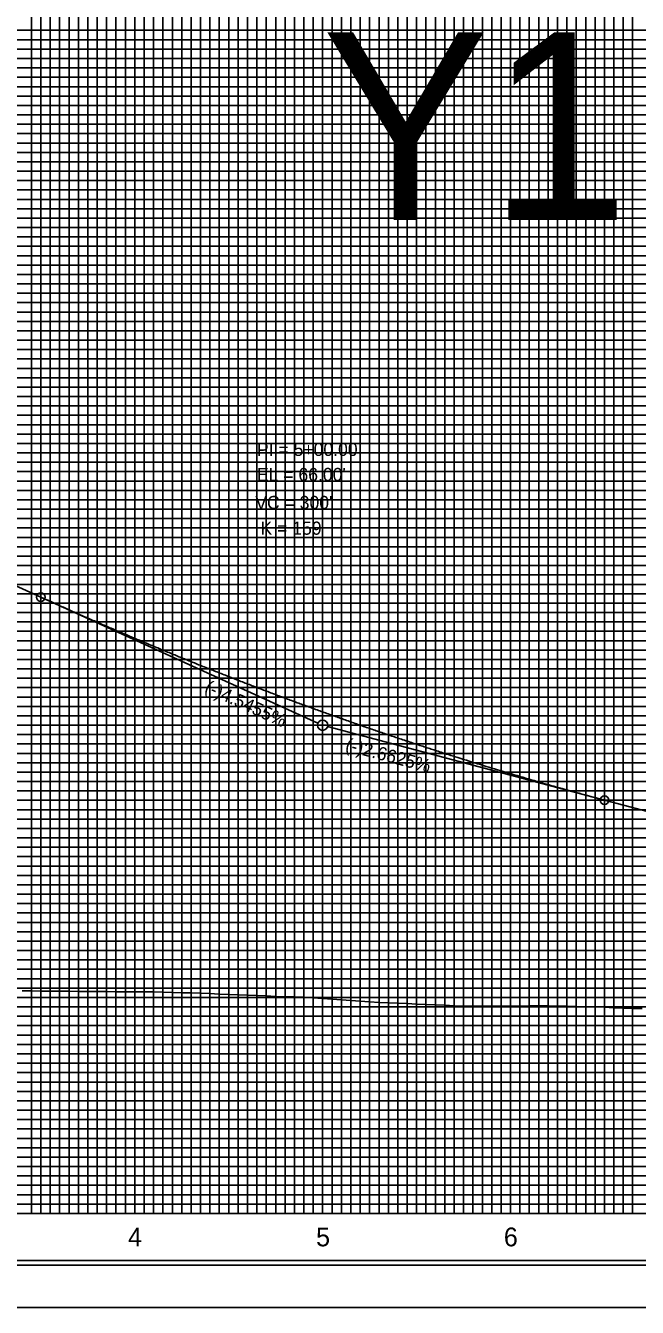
# Model space of a CAD drawing. Extents: x 2345490 to 2436403, y 465165 to 573888.
# Drawn here: x 2411237 to 2411563, y 514181 to 514864 of the extents above; entities that cross this region are included whole.
import ezdxf

# ---------------------------------------------------------------- set-up
doc = ezdxf.new("R2010")
doc.units = 0
for name, color, linetype in [('Old_Level_1', 7, 'Continuous'), ('Old_Level_18', 7, 'Continuous'), ('Old_Level_2', 7, 'Continuous'), ('Old_Level_3', 7, 'Continuous'), ('Old_Level_41', 7, 'Continuous'), ('Old_Level_42', 7, 'Continuous'), ('Old_Level_43', 7, 'Continuous'), ('Old_Level_50', 7, 'Continuous'), ('Old_Level_51', 7, 'Continuous'), ('Old_Level_63', 7, 'Continuous')]:
    doc.layers.add(name, color=color, linetype=linetype)

msp = doc.modelspace()

# ---------------------------------------------------------------- linework, layer by layer
at = {"layer": 'Old_Level_1'}
for points in [[(2411235.325, 514349.732), (2411240.325, 514349.688), (2411245.325, 514349.64475), (2411250.325, 514349.60225), (2411255.325, 514349.5605), (2411260.325, 514349.5195), (2411265.325, 514349.479), (2411270.325, 514349.437), (2411275.325, 514349.393), (2411280.325, 514349.34975), (2411285.325, 514349.3075), (2411290.325, 514349.26575), (2411295.325, 514349.225), (2411300.325, 514349.185), (2411305.325, 514349.1425), (2411310.325, 514349.02275), (2411315.325, 514348.9005), (2411320.325, 514348.776), (2411325.325, 514348.649), (2411330.325, 514348.471), (2411335.325, 514348.2715), (2411340.325, 514348.0695), (2411345.325, 514347.86525), (2411350.325, 514347.65875), (2411355.325, 514347.45025), (2411360.325, 514347.2395), (2411365.325, 514347.02675), (2411370.325, 514346.81225), (2411375.325, 514346.61625), (2411380.325, 514346.5435), (2411385.325, 514346.30175), (2411390.325, 514345.9535), (2411395.325, 514345.60675)], [(2411395.325, 514345.60675), (2411400.325, 514345.26175), (2411405.325, 514344.91875), (2411410.325, 514344.57775), (2411415.325, 514344.23875), (2411420.325, 514343.902), (2411425.325, 514343.56775), (2411430.325, 514343.337), (2411435.325, 514343.16325), (2411440.325, 514342.958), (2411445.325, 514342.72575), (2411450.325, 514342.49925), (2411455.325, 514342.278), (2411460.325, 514342.0625), (2411465.325, 514341.8525), (2411470.325, 514341.64825), (2411475.325, 514341.56575), (2411480.325, 514341.5685), (2411485.325, 514341.57875), (2411490.325, 514341.59675), (2411495.325, 514341.6225), (2411500.325, 514341.67525), (2411505.325, 514341.737), (2411510.325, 514341.80625), (2411515.325, 514341.82275), (2411520.325, 514341.684), (2411525.325, 514341.55175), (2411530.325, 514341.4255), (2411535.325, 514341.30575), (2411540.325, 514341.192), (2411545.325, 514341.05125), (2411550.325, 514340.777), (2411555.325, 514340.512), (2411560.325, 514340.421), (2411565.325, 514340.27075)]]:
    msp.add_lwpolyline(points, dxfattribs=at)
at = {"layer": 'Old_Level_18'}
msp.add_lwpolyline([(2412345.325, 515256.21425), (2410845.325, 515256.21425), (2410845.325, 514206.21425), (2412345.325, 514206.21425)], close=True, dxfattribs=at)
at = {"layer": 'Old_Level_2'}
for p, q in [((2411183.325, 514587.57825), (2411245.325, 514559.3965)), ((2411245.325, 514559.3965), (2411392.8215, 514492.3525)), ((2411545.325, 514451.277), (2411397.9825, 514490.507)), ((2411545.325, 514451.277), (2411625.325, 514429.977))]:
    msp.add_line(p, q, dxfattribs=at)
for centre, radius in [((2411245.325, 514559.3965), 2.25), ((2411395.325, 514491.2145), 2.75), ((2411545.325, 514451.277), 2.25)]:
    msp.add_circle(centre, radius, dxfattribs=at)
msp.add_spline([(2411245.325, 514559.3965), (2411251.325, 514556.6805), (2411257.325, 514553.987), (2411263.325, 514551.31625), (2411269.325, 514548.668), (2411275.325, 514546.0425), (2411281.325, 514543.4395), (2411287.325, 514540.859), (2411293.325, 514538.30125), (2411299.325, 514535.766), (2411305.325, 514533.2535), (2411311.325, 514530.7635), (2411317.325, 514528.296), (2411323.325, 514525.85125), (2411329.325, 514523.429), (2411335.325, 514521.02925), (2411341.325, 514518.65225), (2411347.325, 514516.29775), (2411353.325, 514513.966), (2411359.325, 514511.65675), (2411365.325, 514509.37), (2411371.325, 514507.106), (2411377.325, 514504.8645), (2411383.325, 514502.64575), (2411389.325, 514500.4495), (2411395.325, 514498.27575), (2411401.325, 514496.1245), (2411407.325, 514493.996), (2411413.325, 514491.89025), (2411419.325, 514489.807), (2411425.325, 514487.74625), (2411431.325, 514485.708), (2411437.325, 514483.6925), (2411443.325, 514481.69975), (2411449.325, 514479.72925), (2411455.325, 514477.7815), (2411461.325, 514475.8565), (2411467.325, 514473.954), (2411473.325, 514472.074), (2411479.325, 514470.21675), (2411485.325, 514468.382), (2411491.325, 514466.56975), (2411497.325, 514464.78025), (2411503.325, 514463.01325), (2411509.325, 514461.26875), (2411515.325, 514459.547), (2411521.325, 514457.848), (2411527.325, 514456.17125), (2411533.325, 514454.51725), (2411539.325, 514452.886), (2411545.325, 514451.277)], degree=3, dxfattribs=at)
at = {"layer": 'Old_Level_41'}
msp.add_line((2412345.325, 514231.21425), (2410845.325, 514231.21425), dxfattribs=at)
for points in [[(2411195.325, 514231.21425), (2411245.325, 514231.21425), (2411245.325, 515256.21425)], [(2411270.325, 515256.21425), (2411270.325, 514231.21425), (2411320.325, 514231.21425), (2411320.325, 515256.21425)], [(2411295.325, 515256.21425), (2411295.325, 514231.21425), (2411345.325, 514231.21425), (2411345.325, 515256.21425)], [(2411370.325, 515256.21425), (2411370.325, 514231.21425), (2411420.325, 514231.21425), (2411420.325, 515256.21425)], [(2411395.325, 515256.21425), (2411395.325, 514231.21425), (2411445.325, 514231.21425), (2411445.325, 515256.21425)], [(2411470.325, 515256.21425), (2411470.325, 514231.21425), (2411520.325, 514231.21425), (2411520.325, 515256.21425)], [(2411495.325, 515256.21425), (2411495.325, 514231.21425), (2411545.325, 514231.21425), (2411545.325, 515256.21425)], [(2412345.325, 514856.21425), (2410845.325, 514856.21425), (2410845.325, 514806.21425), (2412345.325, 514806.21425)], [(2412345.325, 514756.21425), (2410845.325, 514756.21425), (2410845.325, 514706.21425), (2412345.325, 514706.21425)], [(2412345.325, 514656.21425), (2410845.325, 514656.21425), (2410845.325, 514606.21425), (2412345.325, 514606.21425)], [(2412345.325, 514581.21425), (2410845.325, 514581.21425), (2410845.325, 514631.21425), (2412345.325, 514631.21425)], [(2412345.325, 514556.21425), (2410845.325, 514556.21425), (2410845.325, 514506.21425), (2412345.325, 514506.21425)], [(2412345.325, 514481.21425), (2410845.325, 514481.21425), (2410845.325, 514531.21425), (2412345.325, 514531.21425)], [(2412345.325, 514456.21425), (2410845.325, 514456.21425), (2410845.325, 514406.21425), (2412345.325, 514406.21425)], [(2412345.325, 514356.21425), (2410845.325, 514356.21425), (2410845.325, 514306.21425), (2412345.325, 514306.21425)], [(2412345.325, 514281.21425), (2410845.325, 514281.21425), (2410845.325, 514331.21425), (2412345.325, 514331.21425)], [(2412345.325, 514256.21425), (2410845.325, 514256.21425)]]:
    msp.add_lwpolyline(points, dxfattribs=at)
at = {"layer": 'Old_Level_42'}
for points in [[(2412345.325, 514781.21425), (2410845.325, 514781.21425), (2410845.325, 514831.21425), (2412345.325, 514831.21425)], [(2412345.325, 514681.21425), (2410845.325, 514681.21425), (2410845.325, 514731.21425), (2412345.325, 514731.21425)], [(2412345.325, 514381.21425), (2410845.325, 514381.21425), (2410845.325, 514431.21425), (2412345.325, 514431.21425)]]:
    msp.add_lwpolyline(points, dxfattribs=at)
at = {"layer": 'Old_Level_43'}
for points in [[(2411225.325, 514231.21425), (2411240.325, 514231.21425), (2411240.325, 515256.21425)], [(2411250.325, 515256.21425), (2411250.325, 514231.21425), (2411255.325, 514231.21425), (2411255.325, 515256.21425)], [(2411260.325, 515256.21425), (2411260.325, 514231.21425), (2411265.325, 514231.21425), (2411265.325, 515256.21425)], [(2411275.325, 515256.21425), (2411275.325, 514231.21425), (2411280.325, 514231.21425), (2411280.325, 515256.21425)], [(2411285.325, 515256.21425), (2411285.325, 514231.21425), (2411290.325, 514231.21425), (2411290.325, 515256.21425)], [(2411300.325, 515256.21425), (2411300.325, 514231.21425), (2411305.325, 514231.21425), (2411305.325, 515256.21425)], [(2411310.325, 515256.21425), (2411310.325, 514231.21425), (2411315.325, 514231.21425), (2411315.325, 515256.21425)], [(2411325.325, 515256.21425), (2411325.325, 514231.21425), (2411330.325, 514231.21425), (2411330.325, 515256.21425)], [(2411335.325, 515256.21425), (2411335.325, 514231.21425), (2411340.325, 514231.21425), (2411340.325, 515256.21425)], [(2411350.325, 515256.21425), (2411350.325, 514231.21425), (2411355.325, 514231.21425), (2411355.325, 515256.21425)], [(2411360.325, 515256.21425), (2411360.325, 514231.21425), (2411365.325, 514231.21425), (2411365.325, 515256.21425)], [(2411375.325, 515256.21425), (2411375.325, 514231.21425)], [(2411380.325, 515256.21425), (2411380.325, 514231.21425), (2411385.325, 514231.21425), (2411385.325, 515256.21425), (2411390.325, 515256.21425), (2411390.325, 514231.21425), (2411400.325, 514231.21425), (2411400.325, 515256.21425), (2411405.325, 515256.21425), (2411405.325, 514231.21425), (2411410.325, 514231.21425), (2411410.325, 515256.21425), (2411415.325, 515256.21425), (2411415.325, 514231.21425)], [(2411425.325, 514231.21425), (2411425.325, 515256.21425)], [(2411430.325, 515256.21425), (2411430.325, 514231.21425), (2411435.325, 514231.21425), (2411435.325, 515256.21425)], [(2411440.325, 515256.21425), (2411440.325, 514231.21425), (2411450.325, 514231.21425), (2411450.325, 515256.21425)], [(2411455.325, 515256.21425), (2411455.325, 514231.21425), (2411455.325, 514231.21425), (2411460.325, 514231.21425), (2411460.325, 515256.21425)], [(2411465.325, 515256.21425), (2411465.325, 514231.21425), (2411475.325, 514231.21425), (2411475.325, 515256.21425)], [(2411480.325, 515256.21425), (2411480.325, 514231.21425), (2411485.325, 514231.21425), (2411485.325, 515256.21425)], [(2411490.325, 515256.21425), (2411490.325, 514231.21425), (2411500.325, 514231.21425), (2411500.325, 515256.21425)], [(2411505.325, 515256.21425), (2411505.325, 514231.21425), (2411510.325, 514231.21425), (2411510.325, 515256.21425)], [(2411515.325, 515256.21425), (2411515.325, 514231.21425), (2411525.325, 514231.21425), (2411525.325, 515256.21425)], [(2411530.325, 515256.21425), (2411530.325, 514231.21425), (2411535.325, 514231.21425), (2411535.325, 515256.21425)], [(2411540.325, 515256.21425), (2411540.325, 514231.21425), (2411550.325, 514231.21425), (2411550.325, 515256.21425)], [(2411555.325, 515256.21425), (2411555.325, 514231.21425), (2411560.325, 514231.21425), (2411560.325, 515256.21425)], [(2412295.325, 514861.21425), (2410895.325, 514861.21425), (2410895.325, 514851.21425), (2412295.325, 514851.21425)], [(2412295.325, 514846.21425), (2410895.325, 514846.21425), (2410895.325, 514841.21425), (2412295.325, 514841.21425)], [(2412295.325, 514836.21425), (2410895.325, 514836.21425), (2410895.325, 514826.21425), (2412295.325, 514826.21425)], [(2412295.325, 514821.21425), (2410895.325, 514821.21425), (2410895.325, 514816.21425), (2412295.325, 514816.21425)], [(2412295.325, 514811.21425), (2410895.325, 514811.21425), (2410895.325, 514801.21425), (2412295.325, 514801.21425)], [(2412295.325, 514796.21425), (2410895.325, 514796.21425), (2410895.325, 514791.21425), (2412295.325, 514791.21425)], [(2412295.325, 514786.21425), (2410895.325, 514786.21425), (2410895.325, 514776.21425), (2412295.325, 514776.21425)], [(2412295.325, 514771.21425), (2410895.325, 514771.21425), (2410895.325, 514766.21425), (2412295.325, 514766.21425)], [(2412295.325, 514761.21425), (2410895.325, 514761.21425), (2410895.325, 514751.21425), (2412295.325, 514751.21425)], [(2412295.325, 514746.21425), (2410895.325, 514746.21425), (2410895.325, 514741.21425), (2412295.325, 514741.21425)], [(2412295.325, 514736.21425), (2410895.325, 514736.21425)], [(2410895.325, 514726.21425), (2412295.325, 514726.21425)], [(2412295.325, 514721.21425), (2410895.325, 514721.21425), (2410895.325, 514716.21425), (2412295.325, 514716.21425)], [(2412295.325, 514711.21425), (2410895.325, 514711.21425), (2410895.325, 514701.21425), (2412295.325, 514701.21425)], [(2412295.325, 514696.21425), (2410895.325, 514696.21425), (2410895.325, 514691.21425), (2412295.325, 514691.21425)], [(2412295.325, 514686.21425), (2410895.325, 514686.21425), (2410895.325, 514676.21425), (2412295.325, 514676.21425)], [(2412295.325, 514671.21425), (2410895.325, 514671.21425), (2410895.325, 514666.21425), (2412295.325, 514666.21425)], [(2412295.325, 514661.21425), (2410895.325, 514661.21425), (2410895.325, 514651.21425), (2412295.325, 514651.21425)], [(2412295.325, 514646.21425), (2410895.325, 514646.21425), (2410895.325, 514641.21425), (2412295.325, 514641.21425)], [(2412295.325, 514636.21425), (2410895.325, 514636.21425), (2410895.325, 514626.21425), (2412295.325, 514626.21425)], [(2412295.325, 514621.21425), (2410895.325, 514621.21425), (2410895.325, 514616.21425), (2412295.325, 514616.21425)], [(2412295.325, 514611.21425), (2410895.325, 514611.21425), (2410895.325, 514601.21425), (2412295.325, 514601.21425)], [(2412295.325, 514596.21425), (2410895.325, 514596.21425), (2410895.325, 514591.21425), (2412295.325, 514591.21425)], [(2412295.325, 514586.21425), (2410895.325, 514586.21425), (2410895.325, 514576.21425), (2412295.325, 514576.21425)], [(2412295.325, 514571.21425), (2410895.325, 514571.21425), (2410895.325, 514566.21425), (2412295.325, 514566.21425)], [(2412295.325, 514561.21425), (2410895.325, 514561.21425), (2410895.325, 514551.21425), (2412295.325, 514551.21425)], [(2412295.325, 514546.21425), (2410895.325, 514546.21425), (2410895.325, 514541.21425), (2412295.325, 514541.21425)], [(2412295.325, 514536.21425), (2410895.325, 514536.21425), (2410895.325, 514526.21425), (2412295.325, 514526.21425)], [(2412295.325, 514521.21425), (2410895.325, 514521.21425), (2410895.325, 514516.21425), (2412295.325, 514516.21425)], [(2412295.325, 514511.21425), (2410895.325, 514511.21425), (2410895.325, 514501.21425), (2412295.325, 514501.21425)], [(2412295.325, 514496.21425), (2410895.325, 514496.21425), (2410895.325, 514491.21425), (2412295.325, 514491.21425)], [(2412295.325, 514486.21425), (2410895.325, 514486.21425), (2410895.325, 514476.21425), (2412295.325, 514476.21425)], [(2412295.325, 514471.21425), (2410895.325, 514471.21425), (2410895.325, 514466.21425), (2412295.325, 514466.21425)], [(2412295.325, 514461.21425), (2410895.325, 514461.21425), (2410895.325, 514451.21425), (2412295.325, 514451.21425)], [(2412295.325, 514446.21425), (2410895.325, 514446.21425), (2410895.325, 514441.21425), (2412295.325, 514441.21425)], [(2412295.325, 514436.21425), (2410895.325, 514436.21425)], [(2410895.325, 514426.21425), (2412295.325, 514426.21425)], [(2412295.325, 514421.21425), (2410895.325, 514421.21425), (2410895.325, 514416.21425), (2412295.325, 514416.21425)], [(2412295.325, 514411.21425), (2410895.325, 514411.21425)], [(2410895.325, 514401.21425), (2412295.325, 514401.21425)], [(2412295.325, 514396.21425), (2410895.325, 514396.21425), (2410895.325, 514391.21425), (2412295.325, 514391.21425)], [(2412295.325, 514386.21425), (2410895.325, 514386.21425), (2410895.325, 514376.21425), (2412295.325, 514376.21425)], [(2412295.325, 514371.21425), (2410895.325, 514371.21425), (2410895.325, 514366.21425), (2412295.325, 514366.21425)], [(2412295.325, 514361.21425), (2410895.325, 514361.21425), (2410895.325, 514351.21425), (2412295.325, 514351.21425)], [(2412295.325, 514346.21425), (2410895.325, 514346.21425), (2410895.325, 514341.21425), (2412295.325, 514341.21425)], [(2412295.325, 514336.21425), (2410895.325, 514336.21425), (2410895.325, 514326.21425), (2412295.325, 514326.21425)], [(2412295.325, 514321.21425), (2410895.325, 514321.21425), (2410895.325, 514316.21425), (2412295.325, 514316.21425)], [(2412295.325, 514311.21425), (2410895.325, 514311.21425), (2410895.325, 514301.21425), (2412295.325, 514301.21425)], [(2412295.325, 514296.21425), (2410895.325, 514296.21425), (2410895.325, 514291.21425), (2412295.325, 514291.21425)], [(2412295.325, 514286.21425), (2410895.325, 514286.21425), (2410895.325, 514276.21425), (2412295.325, 514276.21425)], [(2412295.325, 514271.21425), (2410895.325, 514271.21425), (2410895.325, 514266.21425), (2412295.325, 514266.21425)], [(2412295.325, 514261.21425), (2410895.325, 514261.21425), (2410895.325, 514251.21425), (2412295.325, 514251.21425)], [(2412295.325, 514246.21425), (2410895.325, 514246.21425), (2410895.325, 514241.21425), (2412295.325, 514241.21425)], [(2412295.325, 514236.21425), (2410895.325, 514236.21425)]]:
    msp.add_lwpolyline(points, dxfattribs=at)
at = {"layer": 'Old_Level_50'}
msp.add_lwpolyline([(2412357.825, 515258.76425), (2410691.325, 515258.76425), (2410691.325, 514203.66425), (2412357.825, 514203.66425)], close=True, dxfattribs=at)
at = {"layer": 'Old_Level_51'}
msp.add_lwpolyline([(2412362.325, 515281.21425), (2410678.325, 515281.21425), (2410678.325, 514181.21425), (2412362.325, 514181.21425)], close=True, dxfattribs=at)
at = {"layer": 'Old_Level_63'}
msp.add_line((2410895.325, 514231.21425), (2412358.114, 514231.21425), dxfattribs=at)

# ---------------------------------------------------------------- texts
at = {"layer": 'Old_Level_1'}
for s, p in [('4', (2411291.731, 514213.7145)), ('5', (2411391.8235, 514213.7145)), ('6', (2411491.7645, 514213.7145))]:
    msp.add_text(s, height=10, dxfattribs=at).set_placement(p)
at = {"layer": 'Old_Level_2'}
for s, height, p in [('PI = 5+00.00', 7.0000005, (2411360.325, 514634.56725)), ("EL = 66.00'", 7.0000005, (2411360.325, 514621.2145)), ("VC = 300'", 7.000001, (2411359.4395, 514606.2925)), ('K = 159', 7.000001, (2411362.22025, 514592.61925))]:
    msp.add_text(s, height=height, dxfattribs=at).set_placement(p)
for s, rotation, p in [('(-)4.5455%', 335.55604444, (2411331.94575, 514509.039)), ('(-)2.6625%', 345.09087222, (2411406.96275, 514477.76775))]:
    msp.add_text(s, height=7.000001, rotation=rotation, dxfattribs=at).set_placement(p)
at = {"layer": 'Old_Level_3'}
msp.add_text('Y1LPB', height=99.999999, dxfattribs=at).set_placement((2411394.85875, 514760.201))

doc.saveas('drawing.dxf')
